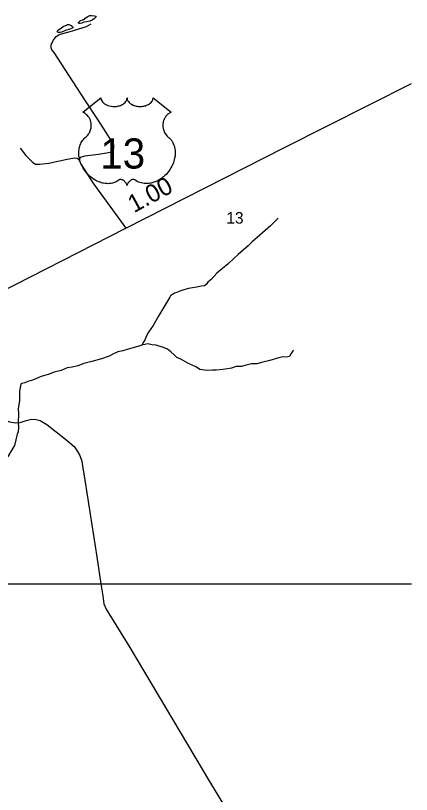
# Model space of a CAD drawing. Extents: x 2315291 to 2336543, y 597177 to 615230.
# Drawn here: x 2333257 to 2336050, y 609266 to 614764 of the extents above; entities that cross this region are included whole.
import ezdxf

# ---------------------------------------------------------------- set-up
doc = ezdxf.new("R2010")
doc.units = 0
for name, color, linetype in [('Exist Hydrographic Misc Water Feature', 7, 'Continuous'), ('Exist Road Non-System Type 51', 7, 'Continuous'), ('Exist Road Primary US Attributed', 7, 'Continuous'), ('Exist Road Primary US Label', 7, 'Continuous'), ('Exist Road Primary US Mileage Tenths English Label', 7, 'Continuous'), ('Exist Road Primary US Shield CELL', 7, 'Continuous'), ('Exist Road Primary US Shield Number Label', 7, 'Continuous'), ('Map Preparation Inset Cut Line', 7, 'Continuous')]:
    doc.layers.add(name, color=color, linetype=linetype)

msp = doc.modelspace()

# ---------------------------------------------------------------- linework, layer by layer
at = {"layer": 'Exist Hydrographic Misc Water Feature'}
for points in [[(2333792.7, 614764.2), (2333814.6, 614762.6), (2333824.9, 614760.6), (2333820.6, 614750.7), (2333814.6, 614742.7), (2333797.2, 614732.4), (2333781.4, 614724.2), (2333759.1, 614719.8), (2333739.2, 614717.5), (2333723.2, 614711.4), (2333713.1, 614707.3), (2333707.2, 614707.3), (2333701, 614711.1), (2333701.2, 614715.1), (2333715.2, 614729.3), (2333723.2, 614731.3), (2333732.8, 614735.5), (2333740.6, 614737.6), (2333748.8, 614745.7), (2333766.7, 614758), (2333780.4, 614764.1), (2333788.4, 614764.1), (2333792.7, 614764.2)], [(2333627.4, 614702.3), (2333631.3, 614700.5), (2333639.5, 614698.5), (2333649.4, 614694.6), (2333657.6, 614686.8), (2333659.8, 614682.8), (2333659.6, 614678.8), (2333639.5, 614668.5), (2333608.2, 614658.2), (2333588.1, 614649.9), (2333571.7, 614643.8), (2333560.2, 614645.9), (2333552, 614647.6), (2333550.1, 614651.5), (2333552, 614655.7), (2333555.9, 614661.6), (2333577.6, 614676.2), (2333593.4, 614688), (2333609.4, 614694.5), (2333615.3, 614696.4), (2333623.1, 614700.5), (2333627.4, 614702.3)], [(2335109.5, 613334.9), (2335055.8, 613280.5), (2334980.6, 613214), (2334925.2, 613167.1), (2334897.5, 613138.9), (2334826.4, 613078.2), (2334796.6, 613049.9), (2334757.1, 613011.6), (2334677.9, 612944.8), (2334636.5, 612900.4), (2334614.3, 612881.8), (2334602.7, 612865.7), (2334590.8, 612855.7)], [(2334590.8, 612855.7), (2334566.6, 612853.3), (2334535, 612847.1), (2334504.8, 612842.7), (2334477, 612838.4), (2334445.2, 612828.2), (2334415.4, 612818), (2334395.3, 612809.7), (2334377.7, 612803.4), (2334349.6, 612785.4), (2334345.7, 612777), (2334318, 612728.8), (2334267, 612646.5), (2334228, 612576.1), (2334194.4, 612529.7), (2334178.6, 612497.6), (2334169.4, 612473.5), (2334161.4, 612463.3), (2334149.5, 612443.2), (2334147.6, 612437)], [(2334147.6, 612437), (2334120, 612429), (2334077.9, 612416.2), (2334043.9, 612405.9), (2334014, 612397.9), (2333978.3, 612389.5), (2333942.4, 612373), (2333916.6, 612358.6), (2333862.8, 612342), (2333794.8, 612321.4), (2333739, 612308.6), (2333695.1, 612292.5), (2333655.5, 612281.9), (2333621.3, 612277.7), (2333577.4, 612259.2), (2333529.8, 612246.9), (2333485.9, 612230.4), (2333438, 612215.6), (2333404.1, 612201.3), (2333376.4, 612190.8), (2333342.4, 612180.6), (2333322.9, 612172.5), (2333301, 612166.1), (2333294.8, 612162.2)], [(2335217.2, 612402.6), (2335213.5, 612396.7), (2335201.2, 612378.6), (2335189.7, 612358.5), (2335168, 612352.4), (2335141.9, 612353.9), (2335114.1, 612347.5), (2335050.1, 612328.8), (2335000.5, 612318.4), (2334958.4, 612306.1), (2334922.5, 612305.4), (2334874.6, 612293.2), (2334848.9, 612286.9), (2334812.6, 612286.2), (2334780.8, 612276), (2334721, 612265.6), (2334673.4, 612261), (2334645.3, 612260.7), (2334605.3, 612258.2), (2334573.1, 612263.9), (2334557.1, 612265.5), (2334533.1, 612281.3), (2334472.4, 612310.6), (2334422.2, 612338.1), (2334394.1, 612350), (2334376.1, 612369.7), (2334351.7, 612389.2), (2334327.9, 612409.1), (2334301.6, 612420.7), (2334277.6, 612426.8), (2334247.7, 612438.1), (2334219.4, 612440), (2334189.5, 612445.7), (2334147.6, 612437)], [(2333294.8, 612162.2), (2333285.2, 612112.1), (2333284, 612046.2), (2333274.7, 611988), (2333277.2, 611951.9), (2333276, 611890.1), (2333278.2, 611858.1), (2333274.1, 611826.3), (2333268.6, 611810.1), (2333264.7, 611800.1)], [(2333264.7, 611800.1), (2333258.9, 611768.1), (2333249.7, 611729.8), (2333237.8, 611709.7), (2333224.1, 611685.8), (2333206, 611659.3), (2333190.5, 611635.2), (2333182.7, 611621), (2333171, 611601.3), (2333157.4, 611568.9), (2333155.2, 611550.9), (2333150.1, 611516.8), (2333150.3, 611494.9), (2333150.3, 611482.7), (2333150.7, 611466.9), (2333148.4, 611461.2)]]:
    msp.add_lwpolyline(points, dxfattribs=at)
at = {"layer": 'Exist Road Non-System Type 51'}
for points in [[(2333703.5, 613746.3), (2333716.3, 613763.6), (2333745.2, 613773.6), (2333841.9, 613785.8), (2333927.4, 613799.2), (2333944.1, 613811.4), (2333950.8, 613827), (2333950.8, 613850.3), (2333941.9, 613869.2), (2333911.9, 613913.7), (2333840.8, 614022.7), (2333746.3, 614168.4), (2333580.7, 614423.6), (2333528.5, 614503.7), (2333511.8, 614522.6), (2333507.3, 614535.9), (2333508.4, 614560.4), (2333524, 614590.4), (2333540.7, 614614.9), (2333565.1, 614630.5), (2333640.7, 614651.6), (2333756.3, 614687.2), (2333790.7, 614705)], [(2333290.1, 613828.1), (2333330.1, 613776.4), (2333358.4, 613744.7), (2333378.4, 613726.3), (2333396.8, 613716.3), (2333426.8, 613714.6), (2333490.1, 613723), (2333620.7, 613750.2), (2333675.2, 613759.1), (2333691.8, 613756.9), (2333703.5, 613746.3)], [(2333703.5, 613746.3), (2333718.5, 613713), (2333801.9, 613582.9), (2334035.3, 613262.6)], [(2332609.9, 612536.1), (2332734.9, 612281.7), (2332813.3, 612114.9), (2332833.3, 612083.2), (2332858.3, 612049.8), (2332889.9, 612029.8), (2333023.3, 611973.1), (2333213.4, 611896.3), (2333256.7, 611889.7), (2333290.1, 611891.3), (2333331.7, 611904.7), (2333368.4, 611914.7), (2333401.8, 611913), (2333430.1, 611906.4), (2333476.8, 611876.3), (2333608.5, 611772.9), (2333670.2, 611721.2), (2333693.5, 611687.8), (2333710.2, 611657.8), (2333723.5, 611617.8), (2333728.5, 611584.4), (2333747.6, 611469.5), (2333830.2, 610943.8), (2333859.1, 610753.3)], [(2333859.1, 610753.3), (2333871.9, 610668.6), (2333880.2, 610611.9), (2333895.2, 610572.7), (2334063.6, 610303.3), (2334625.4, 609357.4), (2334712.1, 609213.9), (2334742.1, 609170.6), (2334755.4, 609135.5), (2334755.4, 609097.2), (2334751, 609057.7)]]:
    msp.add_lwpolyline(points, dxfattribs=at)
at = {"layer": 'Exist Road Primary US Attributed'}
msp.add_lwpolyline([(2332686, 612575.2), (2333028.3, 612751.3), (2334035.3, 613262.6), (2335155.6, 613832.5), (2336050.3, 614283.7)], dxfattribs=at)
at = {"layer": 'Exist Road Primary US Shield CELL'}
for p, q in [((2333730.5, 614081.3), (2333859.1, 614183.7)), ((2333859.1, 614183.7), (2333859.4, 614178.4)), ((2333859.4, 614178.4), (2333860.7, 614172.1)), ((2333860.7, 614172.1), (2333861.7, 614168.8)), ((2333861.7, 614168.8), (2333864.7, 614162.6)), ((2333864.7, 614162.6), (2333869.5, 614155.2)), ((2333869.5, 614155.2), (2333876.3, 614148)), ((2333876.3, 614148), (2333884, 614141.7)), ((2333884, 614141.7), (2333889.2, 614138.3)), ((2333889.2, 614138.3), (2333897.9, 614133.6)), ((2334004, 614133.4), (2334011.6, 614137.5)), ((2334011.6, 614137.5), (2334017.8, 614141.4)), ((2334017.8, 614141.4), (2334022.6, 614144.9)), ((2334022.6, 614144.9), (2334029.4, 614151.5)), ((2334029.4, 614151.5), (2334034.9, 614158.2)), ((2334034.9, 614158.2), (2334037.2, 614162)), ((2334037.2, 614162), (2334039.1, 614165.7)), ((2334039.1, 614165.7), (2334041.8, 614173.4)), ((2334041.8, 614173.4), (2334042.6, 614176.9)), ((2334042.6, 614176.9), (2334043.1, 614184)), ((2334043.1, 614184), (2334043.6, 614178)), ((2334043.6, 614178), (2334044.2, 614174.3)), ((2334044.2, 614174.3), (2334045.2, 614170.6)), ((2334045.2, 614170.6), (2334046.7, 614166.7)), ((2334046.7, 614166.7), (2334049.4, 614161.3)), ((2334049.4, 614161.3), (2334052.5, 614156.7)), ((2334052.5, 614156.7), (2334058.2, 614150)), ((2334058.2, 614150), (2334061.8, 614146.6)), ((2334061.8, 614146.6), (2334065, 614144)), ((2334065, 614144), (2334073.8, 614137.9)), ((2334073.8, 614137.9), (2334084, 614132.8)), ((2334187.7, 614133.3), (2334195.7, 614137.5)), ((2334195.7, 614137.5), (2334202.1, 614141.5)), ((2334202.1, 614141.5), (2334206.9, 614145.3)), ((2334206.9, 614145.3), (2334212.5, 614150.5)), ((2334212.5, 614150.5), (2334217.8, 614156.6)), ((2334217.8, 614156.6), (2334220.9, 614161.1)), ((2334220.9, 614161.1), (2334223.1, 614165.8)), ((2334223.1, 614165.8), (2334225.2, 614170.6)), ((2334225.2, 614170.6), (2334226.4, 614175.8)), ((2334226.4, 614175.8), (2334227, 614180.3)), ((2334227, 614180.3), (2334227.1, 614184.1)), ((2334227.1, 614184.1), (2334355.7, 614081.7)), ((2333897.9, 614133.6), (2333907.9, 614129.4)), ((2333907.9, 614129.4), (2333919, 614126.2)), ((2333919, 614126.2), (2333930.3, 614124)), ((2333930.3, 614124), (2333942.7, 614122.6)), ((2333942.7, 614122.6), (2333954.9, 614122.4)), ((2333954.9, 614122.4), (2333968.1, 614123.4)), ((2333968.1, 614123.4), (2333982.7, 614126.2)), ((2333982.7, 614126.2), (2333989.5, 614127.9)), ((2333989.5, 614127.9), (2333997, 614130.5)), ((2333997, 614130.5), (2334004, 614133.4)), ((2334084, 614132.8), (2334089, 614130.6)), ((2334089, 614130.6), (2334094.2, 614128.8)), ((2334094.2, 614128.8), (2334100.7, 614126.8)), ((2334100.7, 614126.8), (2334107.4, 614125.2)), ((2334107.4, 614125.2), (2334114.1, 614124)), ((2334114.1, 614124), (2334121, 614123.1)), ((2334121, 614123.1), (2334127.9, 614122.5)), ((2334127.9, 614122.5), (2334133.6, 614122.4)), ((2334133.6, 614122.4), (2334140.6, 614122.4)), ((2334140.6, 614122.4), (2334147.1, 614122.8)), ((2334147.1, 614122.8), (2334153.7, 614123.6)), ((2334153.7, 614123.6), (2334161, 614124.8)), ((2334161, 614124.8), (2334166.8, 614126.1)), ((2334166.8, 614126.1), (2334174.6, 614128.1)), ((2334174.6, 614128.1), (2334181.6, 614130.7)), ((2334181.6, 614130.7), (2334187.7, 614133.3)), ((2333734.5, 614079.7), (2333730.5, 614081.3)), ((2333740.8, 614076.5), (2333734.5, 614079.7)), ((2333747.3, 614072.6), (2333740.8, 614076.5)), ((2333752.5, 614068.9), (2333747.3, 614072.6)), ((2333758, 614064.6), (2333752.5, 614068.9)), ((2333763.7, 614058.9), (2333758, 614064.6)), ((2333769.3, 614052.5), (2333763.7, 614058.9)), ((2333774.8, 614044.7), (2333769.3, 614052.5)), ((2333779.7, 614036.3), (2333774.8, 614044.7)), ((2333782.7, 614030), (2333779.7, 614036.3)), ((2333785.9, 614021.5), (2333782.7, 614030)), ((2334304.4, 614032.2), (2334300.5, 614021.9)), ((2334306.8, 614037.2), (2334304.4, 614032.2)), ((2334310.1, 614042.9), (2334306.8, 614037.2)), ((2334313.5, 614048.1), (2334310.1, 614042.9)), ((2334317.2, 614053.2), (2334313.5, 614048.1)), ((2334320.2, 614056.8), (2334317.2, 614053.2)), ((2334323.7, 614060.6), (2334320.2, 614056.8)), ((2334327.5, 614064.2), (2334323.7, 614060.6)), ((2334331.3, 614067.6), (2334327.5, 614064.2)), ((2334340.2, 614073.8), (2334331.3, 614067.6)), ((2334345.7, 614077.1), (2334340.2, 614073.8)), ((2334352.7, 614080.5), (2334345.7, 614077.1)), ((2334355.7, 614081.7), (2334352.7, 614080.5)), ((2333787.9, 614014.1), (2333785.9, 614021.5)), ((2333789.5, 614005.6), (2333787.9, 614014.1)), ((2333787.9, 613964.7), (2333789.4, 613972.5)), ((2333789.4, 613972.5), (2333790.4, 613979.9)), ((2333790.5, 613996.7), (2333789.5, 614005.6)), ((2333790.4, 613979.9), (2333790.8, 613989.1)), ((2333790.8, 613989.1), (2333790.5, 613996.7)), ((2334295.9, 613998.4), (2334295.5, 613992.9)), ((2334295.5, 613992.9), (2334295.5, 613987.5)), ((2334295.5, 613987.5), (2334295.8, 613981.8)), ((2334295.8, 613981.8), (2334296.3, 613976.3)), ((2334297.4, 614009.8), (2334295.9, 613998.4)), ((2334296.3, 613976.3), (2334297.3, 613970.6)), ((2334298.6, 614015.4), (2334297.4, 614009.8)), ((2334300.5, 614021.9), (2334298.6, 614015.4)), ((2333761.9, 613915.5), (2333765.8, 613919.9)), ((2333765.8, 613919.9), (2333770.5, 613926)), ((2333770.5, 613926), (2333774.2, 613931.7)), ((2333774.2, 613931.7), (2333777.2, 613936.8)), ((2333777.2, 613936.8), (2333781.1, 613944.3)), ((2333781.1, 613944.3), (2333783.4, 613950)), ((2333783.4, 613950), (2333786.4, 613958.6)), ((2333786.4, 613958.6), (2333787.9, 613964.7)), ((2334297.3, 613970.6), (2334298.2, 613965.6)), ((2334298.2, 613965.6), (2334299.8, 613959.5)), ((2334299.8, 613959.5), (2334302.1, 613952.3)), ((2334302.1, 613952.3), (2334304.9, 613945.4)), ((2334304.9, 613945.4), (2334310.8, 613934.2)), ((2334310.8, 613934.2), (2334318.3, 613922.8)), ((2334318.3, 613922.8), (2334323.7, 613916.4)), ((2333716.4, 613859.8), (2333720.6, 613868.3)), ((2333720.6, 613868.3), (2333724.7, 613875.3)), ((2333724.7, 613875.3), (2333729.8, 613882.9)), ((2333729.8, 613882.9), (2333734.8, 613889.4)), ((2333734.8, 613889.4), (2333741.4, 613896.5)), ((2333741.4, 613896.5), (2333748.2, 613903.1)), ((2333748.2, 613903.1), (2333754.5, 613908.2)), ((2333754.5, 613908.2), (2333761.9, 613915.5)), ((2334323.7, 613916.4), (2334329.1, 613911)), ((2334329.1, 613911), (2334337, 613904.3)), ((2334337, 613904.3), (2334341.3, 613900.5)), ((2334341.3, 613900.5), (2334346.2, 613895.5)), ((2334346.2, 613895.5), (2334354.3, 613886.2)), ((2334354.3, 613886.2), (2334357.5, 613881.8)), ((2334357.5, 613881.8), (2334360.8, 613876.9)), ((2334360.8, 613876.9), (2334363.9, 613871.8)), ((2334363.9, 613871.8), (2334366.9, 613866.3)), ((2334366.9, 613866.3), (2334369.3, 613861.5)), ((2333703.4, 613806.2), (2333704.4, 613816.3)), ((2333704.4, 613816.3), (2333706.1, 613827)), ((2333706.1, 613827), (2333708.2, 613836.2)), ((2333708.2, 613836.2), (2333710.1, 613842.8)), ((2333710.1, 613842.8), (2333712.8, 613850.9)), ((2333712.8, 613850.9), (2333716.4, 613859.8)), ((2334369.3, 613861.5), (2334373.9, 613850.5)), ((2334373.9, 613850.5), (2334377.2, 613839.8)), ((2334377.2, 613839.8), (2334378.7, 613834.2)), ((2334378.7, 613834.2), (2334381.1, 613821.5)), ((2334381.1, 613821.5), (2334382, 613815.3)), ((2334382, 613815.3), (2334383, 613803)), ((2333703.2, 613797.5), (2333703.4, 613806.2)), ((2333703.3, 613787.1), (2333703.2, 613797.5)), ((2333704.1, 613775.8), (2333703.3, 613787.1)), ((2333705.6, 613765.1), (2333704.1, 613775.8)), ((2333707.1, 613757.2), (2333705.6, 613765.1)), ((2333709.5, 613746.2), (2333707.1, 613757.2)), ((2334379.2, 613757.5), (2334377, 613747.6)), ((2334381.9, 613774), (2334379.2, 613757.5)), ((2334383, 613788.1), (2334381.9, 613774)), ((2334383, 613803), (2334383, 613788.1)), ((2333711.2, 613739.9), (2333709.5, 613746.2)), ((2333714.4, 613730), (2333711.2, 613739.9)), ((2333718.2, 613719.6), (2333714.4, 613730)), ((2333723.1, 613708.2), (2333718.2, 613719.6)), ((2333726.8, 613700.4), (2333723.1, 613708.2)), ((2333733.7, 613687.9), (2333726.8, 613700.4)), ((2334359.3, 613700.9), (2334352.5, 613688.4)), ((2334364.5, 613711.5), (2334359.3, 613700.9)), ((2334370.4, 613726.2), (2334364.5, 613711.5)), ((2334373.6, 613736.1), (2334370.4, 613726.2)), ((2334377, 613747.6), (2334373.6, 613736.1)), ((2333738.3, 613680.2), (2333733.7, 613687.9)), ((2333745.6, 613669.6), (2333738.3, 613680.2)), ((2333756.8, 613655), (2333745.6, 613669.6)), ((2333764, 613646.9), (2333756.8, 613655)), ((2333776.2, 613634.5), (2333764, 613646.9)), ((2334318.3, 613643.3), (2334310.7, 613635.6)), ((2334327.8, 613653.7), (2334318.3, 613643.3)), ((2334335.7, 613663.6), (2334327.8, 613653.7)), ((2334342.5, 613672.8), (2334335.7, 613663.6)), ((2334347.9, 613680.9), (2334342.5, 613672.8)), ((2334352.5, 613688.4), (2334347.9, 613680.9)), ((2333784.6, 613626.9), (2333776.2, 613634.5)), ((2333795.9, 613617.7), (2333784.6, 613626.9)), ((2333810.9, 613607.3), (2333795.9, 613617.7)), ((2333823.8, 613600), (2333810.9, 613607.3)), ((2333831.9, 613595.8), (2333823.8, 613600)), ((2333843.6, 613590.7), (2333831.9, 613595.8)), ((2333852.9, 613587.1), (2333843.6, 613590.7)), ((2333861.7, 613584.4), (2333852.9, 613587.1)), ((2333961, 613588.1), (2333954.8, 613585.7)), ((2333966.3, 613590.5), (2333961, 613588.1)), ((2333973.4, 613594.3), (2333966.3, 613590.5)), ((2333979.4, 613598.1), (2333973.4, 613594.3)), ((2333984.9, 613601.9), (2333979.4, 613598.1)), ((2333990.7, 613606.1), (2333984.9, 613601.9)), ((2333995, 613607), (2333990.7, 613606.1)), ((2333998.1, 613607.1), (2333995, 613607)), ((2334001.9, 613606.8), (2333998.1, 613607.1)), ((2334006.5, 613605.7), (2334001.9, 613606.8)), ((2334010.3, 613604.2), (2334006.5, 613605.7)), ((2334014.5, 613602.1), (2334010.3, 613604.2)), ((2334019.6, 613599), (2334014.5, 613602.1)), ((2334024.5, 613595), (2334019.6, 613599)), ((2334028.5, 613591.1), (2334024.5, 613595)), ((2334033, 613586), (2334028.5, 613591.1)), ((2334054.5, 613587.9), (2334052.2, 613585.1)), ((2334057.5, 613591.4), (2334054.5, 613587.9)), ((2334061.9, 613595.6), (2334057.5, 613591.4)), ((2334065.6, 613598.4), (2334061.9, 613595.6)), ((2334070.3, 613601.6), (2334065.6, 613598.4)), ((2334073.9, 613603.5), (2334070.3, 613601.6)), ((2334079.8, 613605.8), (2334073.9, 613603.5)), ((2334085.6, 613607), (2334079.8, 613605.8)), ((2334091.8, 613606.7), (2334085.6, 613607)), ((2334094.3, 613606), (2334091.8, 613606.7)), ((2334098.9, 613603.6), (2334094.3, 613606)), ((2334114.8, 613593.6), (2334098.9, 613603.6)), ((2334124.3, 613588.9), (2334114.8, 613593.6)), ((2334133.6, 613585.3), (2334124.3, 613588.9)), ((2334232.2, 613587.2), (2334213.2, 613581.9)), ((2334243.6, 613591.5), (2334232.2, 613587.2)), ((2334252.4, 613595.3), (2334243.6, 613591.5)), ((2334262.4, 613600.4), (2334252.4, 613595.3)), ((2334274.1, 613607.2), (2334262.4, 613600.4)), ((2334285.9, 613615.1), (2334274.1, 613607.2)), ((2334294.6, 613621.6), (2334285.9, 613615.1)), ((2334300.7, 613626.6), (2334294.6, 613621.6)), ((2334310.7, 613635.6), (2334300.7, 613626.6)), ((2333870.2, 613582.1), (2333861.7, 613584.4)), ((2333878.2, 613580.3), (2333870.2, 613582.1)), ((2333888, 613578.8), (2333878.2, 613580.3)), ((2333895.8, 613578.1), (2333888, 613578.8)), ((2333902.5, 613577.6), (2333895.8, 613578.1)), ((2333909.8, 613577.5), (2333902.5, 613577.6)), ((2333916.7, 613577.8), (2333909.8, 613577.5)), ((2333924.3, 613578.5), (2333916.7, 613577.8)), ((2333931.5, 613579.6), (2333924.3, 613578.5)), ((2333939.6, 613581.2), (2333931.5, 613579.6)), ((2333947.5, 613583.2), (2333939.6, 613581.2)), ((2333954.8, 613585.7), (2333947.5, 613583.2)), ((2334035.9, 613581.9), (2334033, 613586)), ((2334038.6, 613577.4), (2334035.9, 613581.9)), ((2334041, 613572.1), (2334038.6, 613577.4)), ((2334043, 613564), (2334041, 613572.1)), ((2334044.4, 613570.4), (2334043, 613564)), ((2334046.1, 613574.7), (2334044.4, 613570.4)), ((2334047.7, 613578.1), (2334046.1, 613574.7)), ((2334052.2, 613585.1), (2334047.7, 613578.1)), ((2334143.8, 613582.3), (2334133.6, 613585.3)), ((2334153.6, 613580.2), (2334143.8, 613582.3)), ((2334163, 613578.8), (2334153.6, 613580.2)), ((2334173, 613578.1), (2334163, 613578.8)), ((2334183, 613578.1), (2334173, 613578.1)), ((2334190.5, 613578.5), (2334183, 613578.1)), ((2334198.1, 613579.3), (2334190.5, 613578.5)), ((2334206.3, 613580.5), (2334198.1, 613579.3)), ((2334213.2, 613581.9), (2334206.3, 613580.5))]:
    msp.add_line(p, q, dxfattribs=at)
at = {"layer": 'Map Preparation Inset Cut Line'}
for p, q in [((2330518.4, 610753.3), (2333859.1, 610753.3)), ((2333859.1, 610753.3), (2336050.3, 610753.3))]:
    msp.add_line(p, q, dxfattribs=at)

# ---------------------------------------------------------------- texts
at = {"layer": 'Exist Road Primary US Label'}
msp.add_text('13', height=82.02, dxfattribs=at).set_placement((2334743.7, 613295.2))
at = {"layer": 'Exist Road Primary US Mileage Tenths English Label'}
msp.add_text('1.00', height=125, rotation=28.5097, dxfattribs=at).set_placement((2334091.9, 613368.4))
at = {"layer": 'Exist Road Primary US Shield Number Label'}
msp.add_text('13', height=212.5, dxfattribs=at).set_placement((2333854.8, 613684.4))

doc.saveas('drawing.dxf')
